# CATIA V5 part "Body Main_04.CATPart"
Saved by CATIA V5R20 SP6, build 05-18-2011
Part number: Body Main_04
Bounding box of the stored display mesh (mm): x 50.003 to 89.997, y -290 to 290, z 480 to 649.98
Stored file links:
  E:\#03 University\#02 영남 이공대\#01 2021\#02 여름 방학\#01 Documents\K-Move Page02 ASD01\Body Main_04.CATPart

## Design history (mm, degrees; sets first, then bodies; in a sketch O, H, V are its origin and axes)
Set1 "Reference Data"
  Point1 "Center Point": (0, 0, 0)
Body1 (main body)
  Body2
    Sketch1 on zx-plane, origin (0, 0, 0), H (-1, 0, 0), V (0, 0, 1)
      circle A1 centre (-70, 630) radius 10
      point P1 (-70, 630)
      arc A2 centre (-70, 630) radius 20 from (-60, 612.6795) to (-80, 612.6795) ccw
      line L1 (-60, 612.6795) -> (-60, 480)
      line L2 (-60, 480) -> (-80, 480)
      line L3 (-80, 480) -> (-80, 612.6795)
      construction line L4 (-70, 630) -> (-70, 520.291)
      radius A2 = 20
      radius A1 = 10
      distance P1 H = 630
      distance V P1 = 70
      distance L3 L1 = 20
      distance L2 P1 = 150
      horizontal: L2 H
      vertical: L1 V, L3 V, L4 V
      symmetry: L3 L1 L4
    Pad1: profile Sketch1, direction (0, 1, 0), length 290, mirrored extent
  Assemble1: tool Body2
